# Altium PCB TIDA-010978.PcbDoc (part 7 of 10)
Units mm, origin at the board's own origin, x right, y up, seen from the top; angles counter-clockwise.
Board outline 243.95 x 94.85 mm, 4 copper layers (Top Layer, Mid Layer 1, Mid Layer 2, Bottom Layer), stack 1.623 mm thick; 865 components, 374 nets, 2308 pads, 2132 vias.
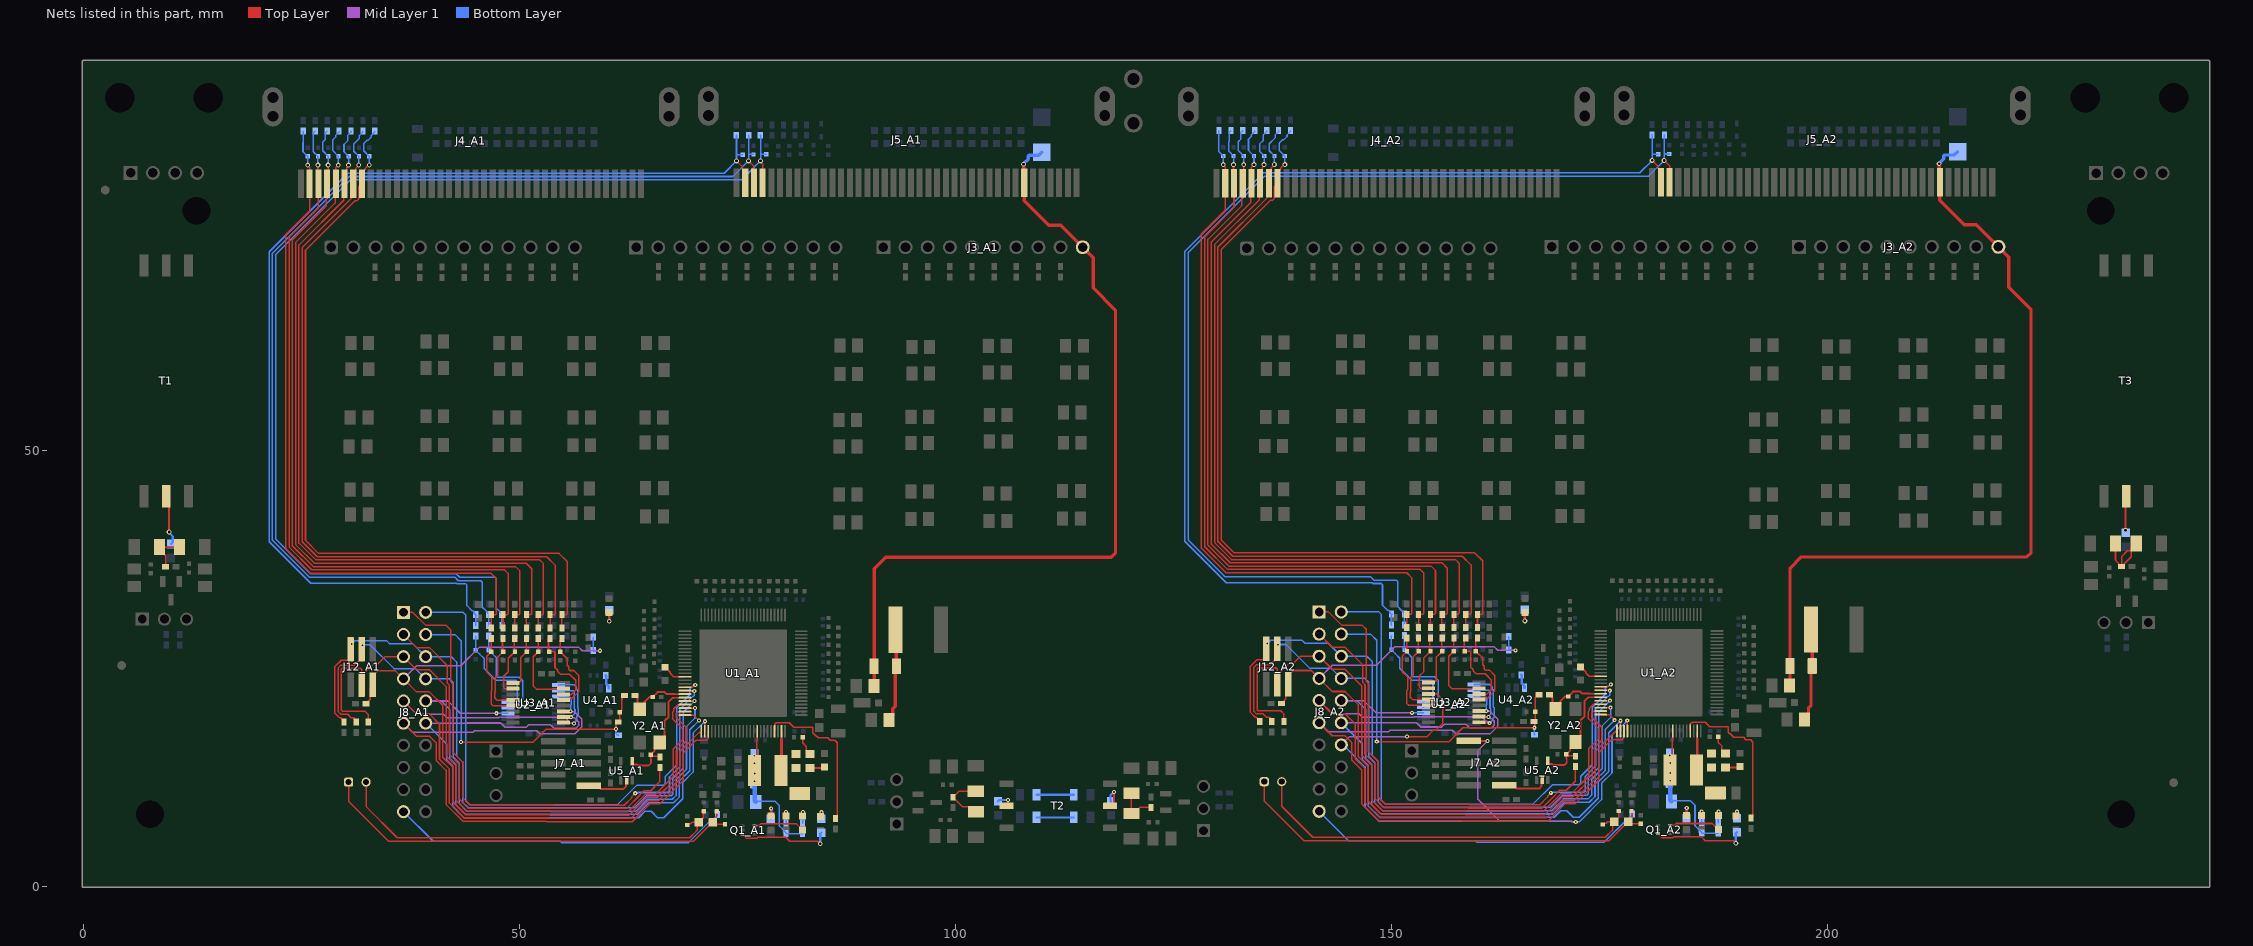
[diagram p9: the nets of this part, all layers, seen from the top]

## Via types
v1: diameter 0.559, hole 0.305, Top Layer to Bottom Layer, tented both sides, 1735 vias
v2: diameter 0.47, hole 0.2, Top Layer to Bottom Layer, tented both sides, 269 vias
v3: diameter 0.5, hole 0.2, Top Layer to Bottom Layer, tented both sides, 128 vias

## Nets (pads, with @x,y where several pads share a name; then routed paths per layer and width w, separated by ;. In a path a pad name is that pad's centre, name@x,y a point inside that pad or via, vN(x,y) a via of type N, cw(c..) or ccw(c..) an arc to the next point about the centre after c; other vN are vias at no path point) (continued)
GPIO8_A2: J7_A2.10 J8_A2.14 U1_A2.79 U3_A2.3 | length 87.7
  Top Layer w0.178: v2(151.794,17.184) 151.839,17.139 154.041,17.139 154.831,17.929 155.107,17.929 155.896,18.718 155.896,21.374 155.182,22.088 154.257,22.088 U3_A2.3@154.243,22.074 ; v2(177.036,19.003) 177.046,18.993 177.046,17.834 U1_A2.79@177.057,17.824
  Top Layer w0.254: J7_A2.10@158.86,16.691 158.867,16.684 160.992,16.684 v2(160.999,16.677)
  Mid Layer 1 w0.178: J8_A2.14@144.243,16.231 145.196,17.184 v2(151.794,17.184) ; v2(160.999,16.677) 159.914,15.592 159.914,9.994 162.459,7.45 170.674,7.45 170.692,7.432 171.096,7.432 v2(171.135,7.394)
  Bottom Layer w0.178: J8_A2.14@144.243,16.231 144.428,16.231 146.963,13.696 146.963,9.073 148.586,7.45 170.674,7.45 170.692,7.432 171.096,7.432 v2(171.135,7.394) ; v2@171.135,7.377 171.19,7.432 171.577,7.432 174.097,9.952 174.097,11.818 175.288,13.009 175.288,17.367 176.305,18.384 176.431,18.384 177.036,18.989 v2(177.036,19.003)
GPIO9_A1: J8_A1.11 U1_A1.78 U2_A1.11 U3_A1.11 | length 77.6
  Top Layer w0.178: J8_A1.11@36.703,18.721 38.204,17.22 39.673,17.22 40.454,16.439 40.454,14.433 41.585,13.302 41.585,11.503 41.585,9.401 43.521,7.466 53.114,7.466 53.156,7.424 62.936,7.424 64.964,9.452 66.097,9.452 68.762,12.117 68.762,15.277 70.244,16.76 71.447,16.76 71.646,16.958 71.646,17.762 U1_A1.78@71.657,17.774 ; U3_A1.11@55.043,20.073 v2(55.846,20.073)
  Mid Layer 1 w0.178: J8_A1.11@36.703,18.721 37.742,17.682 44.668,17.682 44.835,17.848 51.976,17.848 52.347,17.477 56.345,17.477 57.163,18.295 57.163,19.175 56.321,20.017 55.902,20.017 v2(55.846,20.073)
  Bottom Layer w0.178: U2_A1.11@54.473,21.789 54.599,21.663 55.82,21.663 55.924,21.559 55.924,20.841 55.863,20.78 55.863,20.09 v2(55.846,20.073)
GPIO9_A2: J8_A2.11 U1_A2.78 U2_A2.11 U3_A2.11 | length 77.6
  Top Layer w0.178: J8_A2.11@141.703,18.771 143.204,17.27 144.673,17.27 145.454,16.489 145.454,14.483 146.585,13.352 146.585,11.553 146.585,9.451 148.521,7.516 158.114,7.516 158.156,7.474 167.936,7.474 169.964,9.502 171.097,9.502 173.762,12.167 173.762,15.327 175.244,16.81 176.447,16.81 176.646,17.008 176.646,17.812 U1_A2.78@176.657,17.824 ; U3_A2.11@160.043,20.124 160.046,20.121 160.861,20.121 v2(160.863,20.118)
  Mid Layer 1 w0.178: J8_A2.11@141.703,18.771 142.742,17.732 149.668,17.732 149.835,17.898 156.976,17.898 157.347,17.527 161.345,17.527 162.163,18.345 162.163,19.225 161.325,20.063 160.919,20.063 v2(160.863,20.118)
  Bottom Layer w0.178: U2_A2.11@159.473,21.839 159.599,21.713 160.82,21.713 160.924,21.609 160.924,20.891 160.863,20.83 v2(160.863,20.118)
GPIO10_A1: J8_A1.12 U1_A1.77 U2_A1.10 U3_A1.10 | length 76
  Top Layer w0.178: U3_A1.10@55.043,19.424 55.052,19.414 55.897,19.414 v2(55.906,19.405) ; U1_A1.77@71.257,17.774 71.264,17.78 71.264,18.931 v2(71.271,18.938)
  Mid Layer 1 w0.178: J8_A1.12@39.243,18.721 43.957,18.721 43.971,18.735 47.85,18.735 48.359,18.226 50.752,18.226 51.05,18.525 53.574,18.525 53.955,18.144 56.478,18.144 56.785,18.451 56.785,18.885 56.321,19.35 55.962,19.35 v2(55.906,19.405)
  Bottom Layer w0.178: J8_A1.12@39.243,18.721 41.65,16.314 41.65,14.494 42.341,13.802 42.341,9.18 43.65,7.871 63.669,7.871 64.411,8.613 65.108,8.613 65.842,7.878 66.539,7.878 68.719,10.058 68.719,11.924 69.911,13.116 69.911,17.578 v2(71.271,18.938) ; U2_A1.10@54.473,22.439 54.483,22.449 56.197,22.449 56.302,22.345 56.302,20.357 56.37,20.29 56.37,19.856 55.919,19.405 v2(55.906,19.405)
GPIO10_A2: J8_A2.12 U1_A2.77 U2_A2.10 U3_A2.10 | length 75.9
  Top Layer w0.178: U3_A2.10@160.043,19.474 160.062,19.455 161.103,19.455 v2(161.122,19.436) ; U1_A2.77@176.257,17.824 176.264,17.83 176.264,18.981 v2(176.271,18.988)
  Mid Layer 1 w0.178: J8_A2.12@144.243,18.771 148.957,18.771 148.971,18.785 152.85,18.785 153.359,18.276 155.752,18.276 156.05,18.575 158.574,18.575 158.955,18.194 161.478,18.194 161.785,18.501 161.785,18.935 161.478,19.242 161.395,19.242 161.201,19.436 v2(161.122,19.436)
  Bottom Layer w0.178: J8_A2.12@144.243,18.771 146.65,16.364 146.65,14.544 147.341,13.852 147.341,9.23 148.65,7.921 168.669,7.921 169.411,8.663 170.108,8.663 170.842,7.928 171.539,7.928 173.719,10.108 173.719,11.974 174.911,13.166 174.911,17.628 v2(176.271,18.988) ; U2_A2.10@159.473,22.489 159.483,22.499 161.197,22.499 161.302,22.395 161.302,20.421 161.387,20.335 161.387,19.78 161.122,19.515 v2(161.122,19.436)
GPIO11_A1: J8_A1.9 U1_A1.76 U2_A1.9 U3_A1.9 | length 79
  Top Layer w0.178: J8_A1.9@36.703,21.261 38.204,19.76 39.673,19.76 40.832,18.601 40.832,14.59 41.963,13.458 41.963,11.659 41.963,9.558 43.677,7.844 53.271,7.844 53.312,7.802 62.78,7.802 64.815,9.837 65.948,9.837 68.384,12.274 68.384,15.434 70.594,17.644 70.846,17.644 70.857,17.655 U1_A1.76@70.857,17.774 ; U3_A1.9@55.043,18.774 55.096,18.721 56.208,18.721 v2(56.261,18.668)
  Mid Layer 1 w0.178: J8_A1.9@36.703,21.261 38.204,19.76 41.268,19.76 41.703,19.326 47.565,19.326 47.648,19.409 55.162,19.409 55.847,18.724 56.205,18.724 v2(56.261,18.668)
  Bottom Layer w0.178: U2_A1.9@54.473,23.089 54.483,23.099 56.252,23.099 56.529,22.822 56.529,22.652 56.679,22.502 56.679,20.514 56.747,20.446 56.747,19.699 56.569,19.52 56.569,19.054 56.261,18.747 v2(56.261,18.668)
GPIO11_A2: J8_A2.9 U1_A2.76 U2_A2.9 U3_A2.9 | length 79
  Top Layer w0.178: J8_A2.9@141.703,21.311 143.204,19.81 144.673,19.81 145.832,18.651 145.832,14.64 146.963,13.508 146.963,11.709 146.963,9.608 148.677,7.894 158.271,7.894 158.312,7.852 167.78,7.852 169.815,9.887 170.948,9.887 173.384,12.324 173.384,15.484 175.595,17.694 175.846,17.694 175.857,17.705 U1_A2.76@175.857,17.824 ; U3_A2.9@160.043,18.824 160.096,18.771 161.208,18.771 v2(161.261,18.718)
  Mid Layer 1 w0.178: J8_A2.9@141.703,21.311 143.204,19.81 146.268,19.81 146.703,19.376 152.565,19.376 152.648,19.459 160.359,19.459 160.905,18.912 160.988,18.912 161.182,18.718 v2(161.261,18.718)
  Bottom Layer w0.178: U2_A2.9@159.473,23.139 159.483,23.149 161.252,23.149 161.529,22.872 161.529,22.702 161.679,22.552 161.679,20.577 161.765,20.492 161.765,19.396 161.607,19.239 161.607,19.081 161.261,18.735 v2(161.261,18.718)
GPIO12_A1: J8_A1.10 U1_A1.75 U2_A1.3 | length 62.9
  Top Layer w0.178: U1_A1.75@68.982,19.649 69.972,19.649 70.596,19.024 v2(70.596,19.013)
  Mid Layer 1 w0.178: J8_A1.10@39.243,21.261 41.8,21.261 43.211,19.849 v2(47.348,19.849)
  Bottom Layer w0.178: J8_A1.10@39.243,21.261 41.024,21.261 42.028,20.257 42.028,14.65 42.719,13.959 42.719,12.542 42.719,10.939 42.719,9.336 43.806,8.249 45.409,8.249 47.012,8.249 63.513,8.249 64.871,9.607 67.691,9.607 68.341,10.258 68.341,12.081 69.533,13.272 69.533,17.967 70.579,19.013 v2(70.596,19.013) ; v2(47.348,19.849) 47.353,19.844 48.668,19.844 U2_A1.3@48.673,19.839
GPIO12_A2: J8_A2.10 U1_A2.75 U2_A2.3 | length 62.9
  Top Layer w0.178: U1_A2.75@173.982,19.699 174.972,19.699 175.596,19.074 v2(175.596,19.063)
  Mid Layer 1 w0.178: J8_A2.10@144.243,21.311 146.8,21.311 148.211,19.899 v2(152.348,19.899)
  Bottom Layer w0.178: J8_A2.10@144.243,21.311 146.024,21.311 147.028,20.307 147.028,14.7 147.719,14.009 147.719,12.592 147.719,10.989 147.719,9.386 148.806,8.299 150.409,8.299 152.012,8.299 168.513,8.299 169.871,9.657 172.691,9.657 173.341,10.308 173.341,12.131 174.533,13.322 174.533,18.017 175.579,19.063 v2(175.596,19.063) ; v2(152.348,19.899) 152.353,19.894 153.668,19.894 U2_A2.3@153.673,19.889
GPIO13_A1: C94_A1.1 J8_A1.7 J12_A1.2 R196_A1.1 R236_A1.2 U1_A1.74 | length 89
  Top Layer w0.178: R236_A1.2@32.386,20.93 32.481,21.026 32.481,21.044 32.902,21.464 32.902,22.857 33.248,23.204 33.248,24.229 33.726,24.707 35.797,24.707 J8_A1.7@36.703,23.801 38.204,22.3 39.673,22.3 41.21,20.763 41.21,14.819 42.341,13.688 42.341,11.816 42.341,9.714 43.834,8.221 53.427,8.221 53.469,8.18 62.592,8.18 64.627,10.215 65.791,10.215 68.007,12.43 68.007,15.59 69.115,16.699 69.115,18.209 67.968,19.356 67.968,19.839 68.167,20.037 68.971,20.037 U1_A1.74@68.982,20.049
  Mid Layer 1 w0.178: J8_A1.7@36.703,23.801 38.204,25.302 43.278,25.302 45.42,27.444 56.762,27.444 57.188,27.018 v2(59.232,27.018)
  Bottom Layer w0.178: R196_A1.1@58.452,28.584 58.452,27.065 C94_A1.1@58.455,27.061 58.498,27.018 v2(59.232,27.018)
GPIO13_A2: C94_A2.1 J8_A2.7 J12_A2.2 R196_A2.1 R236_A2.2 U1_A2.74 | length 89
  Top Layer w0.178: R236_A2.2@137.386,20.98 137.481,21.076 137.481,21.094 137.902,21.514 137.902,22.907 138.248,23.254 138.248,24.279 138.726,24.757 140.797,24.757 J8_A2.7@141.703,23.851 143.204,22.35 144.673,22.35 146.21,20.813 146.21,14.869 147.341,13.738 147.341,11.866 147.341,9.764 148.834,8.271 158.427,8.271 158.469,8.23 167.592,8.23 169.627,10.265 170.791,10.265 173.007,12.48 173.007,15.64 174.115,16.749 174.115,18.259 172.968,19.406 172.968,19.889 173.167,20.087 173.971,20.087 U1_A2.74@173.982,20.099
  Mid Layer 1 w0.178: J8_A2.7@141.703,23.851 143.204,25.352 148.278,25.352 150.42,27.494 161.762,27.494 162.188,27.068 v2(164.232,27.068)
  Bottom Layer w0.178: R196_A2.1@163.452,28.634 163.452,27.115 C94_A2.1@163.455,27.111 163.498,27.068 v2(164.232,27.068)
GPIO14_A1: J8_A1.8 J12_A1.3 R235_A1.1 U1_A1.73 | length 76.8
  Top Layer w0.178: R235_A1.1@31.283,18.864 31.072,19.075 31.072,19.35 30.68,19.35 30.302,19.728 29.53,19.728 29.205,20.053 29.205,25.047 29.53,25.372 31.102,25.372 31.901,26.171 J12_A1.3@31.901,27.196 31.999,27.294 v2(31.999,27.665) ; U1_A1.73@68.982,20.449 v2(70.131,20.449)
  Bottom Layer w0.178: v2(31.999,27.665) 32.022,27.687 32.9,27.687 35.605,24.982 38.061,24.982 J8_A1.8@39.243,23.801 41.963,23.801 42.405,23.358 42.405,14.806 43.096,14.115 43.096,12.699 43.096,11.096 43.096,9.493 43.963,8.627 45.566,8.627 47.168,8.627 63.356,8.627 64.714,9.985 67.534,9.985 67.964,10.414 67.964,12.237 69.155,13.429 69.155,18.33 70.131,19.306 v2(70.131,20.449)
GPIO14_A2: J8_A2.8 J12_A2.3 R235_A2.1 U1_A2.73 | length 76.8
  Top Layer w0.178: R235_A2.1@136.283,18.914 136.072,19.125 136.072,19.4 135.68,19.4 135.302,19.778 134.53,19.778 134.205,20.103 134.205,25.097 134.53,25.422 136.102,25.422 136.901,26.221 J12_A2.3@136.901,27.246 136.999,27.344 v2(136.999,27.715) ; U1_A2.73@173.982,20.499 v2(175.131,20.499)
  Bottom Layer w0.178: v2(136.999,27.715) 137.022,27.737 137.9,27.737 140.605,25.032 143.061,25.032 J8_A2.8@144.243,23.851 146.963,23.851 147.405,23.408 147.405,14.856 148.096,14.165 148.096,12.749 148.096,11.146 148.096,9.543 148.963,8.677 150.566,8.677 152.168,8.677 168.356,8.677 169.714,10.035 172.534,10.035 172.964,10.464 172.964,12.287 174.155,13.479 174.155,18.38 175.131,19.356 v2(175.131,20.499)
GPIO15_A1: J8_A1.5 J12_A1.4 R234_A1.1 U1_A1.72 | length 75.9
  Top Layer w0.178: J12_A1.4@31.901,23.126 J12_A1.4@31.901,24.151 ; R234_A1.1@32.668,18.864 32.668,19.706 32.296,20.078 30.487,20.078 30.459,20.106 29.687,20.106 29.583,20.21 29.583,24.89 29.687,24.994 31.796,24.994 31.901,24.89 J12_A1.4@31.901,24.151 ; U1_A1.72@68.982,20.849 68.971,20.837 68.167,20.837 67.7,20.371 67.7,20.105 67.59,19.995 67.59,19.199 68.737,18.052 68.737,16.855 67.629,15.747 67.629,12.587 65.635,10.593 64.452,10.593 64.18,10.321 64.18,10.302 62.435,8.558 53.625,8.558 53.584,8.599 43.99,8.599 42.719,9.871 42.719,13.844 41.588,14.975 41.588,22.925 39.673,24.84 38.204,24.84 J8_A1.5@36.703,26.341 34.571,26.341 33.742,25.512 33.262,25.512 J12_A1.4@31.901,24.151
GPIO15_A2: J8_A2.5 J12_A2.4 R234_A2.1 U1_A2.72 | length 75.9
  Top Layer w0.178: J12_A2.4@136.901,23.176 J12_A2.4@136.901,24.201 ; R234_A2.1@137.668,18.914 137.668,19.756 137.296,20.128 135.487,20.128 135.459,20.156 134.687,20.156 134.583,20.26 134.583,24.94 134.687,25.044 136.796,25.044 136.901,24.94 J12_A2.4@136.901,24.201 ; U1_A2.72@173.982,20.899 173.971,20.887 173.167,20.887 172.7,20.421 172.7,20.155 172.59,20.045 172.59,19.249 173.737,18.102 173.737,16.905 172.629,15.797 172.629,12.637 170.635,10.643 169.452,10.643 169.18,10.371 169.18,10.352 167.435,8.608 158.625,8.608 158.584,8.649 148.99,8.649 147.719,9.921 147.719,13.894 146.588,15.025 146.588,22.975 144.673,24.89 143.204,24.89 J8_A2.5@141.703,26.391 139.571,26.391 138.742,25.562 138.262,25.562 J12_A2.4@136.901,24.201
GPIO16_A1: J8_A1.6 J12_A1.5 R233_A1.1 U1_A1.71 | length 78.6
  Top Layer w0.178: R233_A1.1@29.883,18.864 29.883,18.964 29.496,19.35 29.374,19.35 28.827,19.897 28.827,25.203 29.566,25.942 30.349,25.942 30.631,26.223 J12_A1.5@30.631,27.196 J12_A1.5@30.631,28.221 ; J8_A1.6@39.127,26.341 J8_A1.6@39.243,26.341 ; U1_A1.71@68.982,21.249 v2(70.069,21.249)
  Bottom Layer w0.178: v2(30.763,27.796) 31.156,28.188 34.747,28.188 35.093,27.842 37.742,27.842 J8_A1.6@39.243,26.341 42.173,26.341 42.783,25.731 42.783,14.963 43.474,14.272 43.474,9.649 44.119,9.004 63.2,9.004 64.581,10.386 67.401,10.386 67.586,10.571 67.586,12.394 68.777,13.585 68.777,19.957 v2(70.069,21.249)
GPIO16_A2: J8_A2.6 J12_A2.5 R233_A2.1 U1_A2.71 | length 78.6
  Top Layer w0.178: R233_A2.1@134.883,18.914 134.883,19.014 134.496,19.4 134.374,19.4 133.827,19.947 133.827,25.253 134.566,25.992 135.349,25.992 135.631,26.273 J12_A2.5@135.631,27.246 J12_A2.5@135.631,28.271 ; J8_A2.6@144.127,26.391 J8_A2.6@144.243,26.391 ; U1_A2.71@173.982,21.299 v2(175.069,21.299)
  Bottom Layer w0.178: v2(135.763,27.846) 136.156,28.238 139.747,28.238 140.093,27.892 142.742,27.892 J8_A2.6@144.243,26.391 147.173,26.391 147.783,25.781 147.783,15.013 148.474,14.322 148.474,9.699 149.119,9.054 168.2,9.054 169.581,10.436 172.401,10.436 172.586,10.621 172.586,12.444 173.777,13.635 173.777,20.007 v2(175.069,21.299)
GPIO17_A1: J8_A1.3 R71_A1.2 | length 48.7
  Top Layer w0.178: J8_A1.3@36.703,28.881 38.204,27.38 39.673,27.38 41.722,25.331 41.722,23.326 41.965,23.082 41.965,15.132 43.096,14.001 43.096,12.164 43.096,10.027 44.147,8.977 53.74,8.977 53.782,8.935 62.279,8.935 63.802,10.459 63.802,10.477 64.296,10.971 65.05,10.971 66.073,11.994 66.073,13.593 R71_A1.2@66.111,13.631
GPIO17_A2: J8_A2.3 R71_A2.2 | length 48.8
  Top Layer w0.178: J8_A2.3@141.703,28.931 143.204,27.43 144.673,27.43 146.722,25.381 146.722,23.376 146.965,23.132 146.965,15.182 148.096,14.051 148.096,12.214 148.096,10.077 149.147,9.027 158.74,9.027 158.782,8.985 167.279,8.985 168.802,10.509 168.802,10.527 169.296,11.021 170.05,11.021 171.073,12.044 171.073,13.69 R71_A2.2@171.104,13.721
GPIO17_OSC_A1: C124_A1.1 R71_A1.1 U1_A1.70 U5_A1.4 Y2_A1.1 | length 13.8
  Top Layer w0.178: C124_A1.1@65.047,15.088 65.208,14.927 65.488,14.927 65.506,14.91 65.983,14.91 66.032,14.91 R71_A1.1@66.111,14.831 ; 67.591,21.618 67.617,21.644 68.965,21.644 U1_A1.70@68.971,21.637
  Top Layer w0.203: U5_A1.4@62.937,14.357 62.937,14.082 63.035,13.984 63.43,13.984 63.555,13.859 64.82,13.859 65.09,14.128 65.09,14.573 65.047,14.615 C124_A1.1@65.047,15.088 65.496,15.537 65.496,15.915 Y2_A1.1@66.094,16.513
  Top Layer w0.229: Y2_A1.1@66.094,16.513 66.66,17.079 66.66,18.999 66.86,19.199 66.896,19.199 67.114,19.417 67.114,21.159 67.574,21.618 67.591,21.618
GPIO17_OSC_A2: C124_A2.1 R71_A2.1 U1_A2.70 U5_A2.4 Y2_A2.1 | length 13.8
  Top Layer w0.178: C124_A2.1@170.047,15.138 170.208,14.977 170.488,14.977 170.506,14.96 171.066,14.96 R71_A2.1@171.104,14.921 ; 172.591,21.668 172.617,21.694 173.965,21.694 U1_A2.70@173.971,21.687
  Top Layer w0.203: U5_A2.4@167.937,14.407 167.937,14.132 168.035,14.034 168.43,14.034 168.555,13.909 169.82,13.909 170.09,14.178 170.09,14.623 170.047,14.665 C124_A2.1@170.047,15.138 170.496,15.587 170.496,15.965 Y2_A2.1@171.094,16.563
  Top Layer w0.229: Y2_A2.1@171.094,16.563 171.66,17.129 171.66,19.049 171.86,19.249 171.896,19.249 172.114,19.467 172.114,21.209 172.574,21.668 172.591,21.668
GPIO18_A1: C155_A1.2 J8_A1.4 R56_A1.1 R76_A1.2 R77_A1.2 | length 39.8
  Top Layer w0.178: v2(43.307,16.545) 51.59,16.545 53.084,18.038 v2(61.074,18.038) 61.074,18.633 61.392,18.951 61.446,18.951 61.494,19 61.483,19.011 C155_A1.2@61.483,19.948 ; C155_A1.2@61.483,19.959 61.722,20.197 61.722,21.376 61.761,21.415 61.761,21.671 61.972,21.882 R77_A1.2@62.067,21.882 ; R77_A1.2@61.856,22.051 R77_A1.2@62.028,21.88
  Bottom Layer w0.178: J8_A1.4@39.243,28.881 42.594,28.881 43.307,28.168 v2(43.307,16.545) ; v2(61.074,18.038) 61.074,17.552 61.285,17.341 R56_A1.1@61.367,17.341
GPIO18_A2: C155_A2.2 J8_A2.4 R56_A2.1 R76_A2.2 R77_A2.2 | length 39.9
  Top Layer w0.178: v2(148.307,16.595) 156.59,16.595 158.181,18.185 v2(166.384,18.185) 166.446,18.185 166.446,19.001 166.494,19.05 166.483,19.061 C155_A2.2@166.483,19.998 ; C155_A2.2@166.483,20.009 166.494,20.02 166.494,20.777 166.502,20.784 166.502,21.651 166.81,21.959 R77_A2.2@166.81,21.964 ; R77_A2.2@166.604,22.175 166.815,21.964 R77_A2.2@166.915,21.964
  Bottom Layer w0.178: J8_A2.4@144.243,28.931 147.594,28.931 148.307,28.218 v2(148.307,16.595) ; v2(166.384,18.185) 166.384,17.424 R56_A2.1@166.417,17.391
GPIO18_OSC_A1: C128_A1.1 R77_A1.1 U1_A1.69 Y2_A1.3 | length 8.2
  Top Layer w0.178: 67.795,22.047 U1_A1.69@68.98,22.047
  Top Layer w0.229: R77_A1.1@63.267,21.882 63.367,21.882 63.552,21.696 63.552,20.762 63.557,20.757 63.454,20.654 Y2_A1.3@63.794,20.313 64.367,20.886 64.367,21.189 64.921,21.742 65.251,21.742 C128_A1.1@65.272,21.722 65.836,22.286 66.652,22.286 66.891,22.047 67.795,22.047
GPIO18_OSC_A2: C128_A2.1 R77_A2.1 U1_A2.69 Y2_A2.3 | length 8.2
  Top Layer w0.178: 172.795,22.097 U1_A2.69@173.98,22.097
  Top Layer w0.229: R77_A2.1@168.115,21.964 168.215,21.964 168.401,21.779 168.401,21.688 168.454,21.635 168.454,20.704 Y2_A2.3@168.794,20.363 169.367,20.936 169.367,21.239 169.921,21.792 170.251,21.792 C128_A2.1@170.272,21.772 170.836,22.336 171.652,22.336 171.891,22.097 172.795,22.097
GPIO19_A1: J8_A1.1 U1_A1.68 | length 65.3
  Top Layer w0.178: J8_A1.1@36.703,31.421 37.774,31.421 39.275,29.92 41.614,29.92 42.099,29.434 42.099,23.482 42.343,23.238 42.343,15.403 43.474,14.272 43.474,10.184 44.303,9.355 53.897,9.355 53.938,9.313 62.026,9.313 62.9,10.187 62.9,10.298 v2(63.278,10.676) ; U1_A1.68@68.35,22.437 68.361,22.449 U1_A1.68@68.982,22.449 68.993,22.437 69.999,22.437 v2(70.04,22.396)
  Bottom Layer w0.178: v2(63.278,10.676) 63.334,10.731 63.539,10.731 63.571,10.764 67.104,10.764 67.208,10.868 67.208,12.55 68.399,13.742 68.399,20.32 69.852,21.772 69.936,21.772 70.04,21.877 v2(70.04,22.396)
GPIO19_A2: J8_A2.1 U1_A2.68 | length 65.3
  Top Layer w0.178: J8_A2.1@141.703,31.471 142.774,31.471 144.275,29.97 146.614,29.97 147.099,29.484 147.099,23.532 147.343,23.288 147.343,15.453 148.474,14.322 148.474,10.234 149.303,9.405 158.897,9.405 158.938,9.363 167.026,9.363 167.9,10.237 167.9,10.348 v2(168.278,10.726) ; U1_A2.68@173.35,22.487 173.361,22.499 U1_A2.68@173.982,22.499 173.993,22.487 174.999,22.487 v2(175.04,22.446)
  Bottom Layer w0.178: v2(168.278,10.726) 168.334,10.781 168.539,10.781 168.571,10.814 172.104,10.814 172.208,10.918 172.208,12.6 173.399,13.792 173.399,20.37 174.852,21.822 174.936,21.822 175.04,21.927 v2(175.04,22.446)
GPIO20_A1: J8_A1.2 U1_A1.67 | length 64.2
  Top Layer w0.178: U1_A1.67@68.982,22.849 68.993,22.86 69.797,22.86 69.969,23.031 70.1,23.031 v2(70.156,23.087)
  Bottom Layer w0.178: J8_A1.2@39.243,31.421 43.566,31.421 43.852,31.134 43.852,9.806 44.276,9.382 61.244,9.382 63.478,11.616 66.523,11.616 66.697,11.791 66.697,12.574 68.022,13.898 68.022,20.476 69.517,21.971 69.517,22.633 69.803,22.919 69.91,22.919 70.077,23.087 v2(70.156,23.087)
GPIO20_A2: J8_A2.2 U1_A2.67 | length 64.2
  Top Layer w0.178: U1_A2.67@173.982,22.899 173.993,22.91 174.797,22.91 174.969,23.081 175.1,23.081 v2(175.156,23.137)
  Bottom Layer w0.178: J8_A2.2@144.243,31.471 148.566,31.471 148.852,31.184 148.852,9.856 149.276,9.432 166.244,9.432 168.478,11.666 171.523,11.666 171.697,11.841 171.697,12.624 173.022,13.948 173.022,20.526 174.517,22.021 174.517,22.683 174.803,22.969 174.91,22.969 175.077,23.137 v2(175.156,23.137)
GPIO_R_A1: J8_A1.19 R105_A1.1 | length 38.8
  Bottom Layer w0.178: J8_A1.19@36.703,8.561 40.102,5.162 54.672,5.162 54.816,5.017 69.386,5.017 72.086,7.718 72.247,7.718 72.697,8.168 R105_A1.1@72.697,8.226
GPIO_R_A2: J8_A2.19 R105_A2.1 | length 38.8
  Bottom Layer w0.178: J8_A2.19@141.703,8.611 145.102,5.212 159.672,5.212 159.816,5.067 174.386,5.067 177.085,7.766 177.201,7.766 177.609,8.174 R105_A2.1@177.609,8.274
LDOIN_A1: C11_A1.2 C16_A1.2 C17_A1.2 C18_A1.1 L2_A1.2 R126_A1.2 R129_A1.2 U1_A1.92 | length 15.5
  Top Layer w0.178: L2_A1.2@76.943,13.29 77.202,13.549 77.202,16.769 77.257,16.824 U1_A1.92@77.257,17.774
  Bottom Layer w0.178: C18_A1.1@77.096,9.691 77.179,9.774 79.29,9.774 79.81,9.255 79.81,6.914 80.153,6.571 80.161,6.571 80.572,6.16 R129_A1.2@80.572,6.06 R126_A1.2@82.468,6.06
  Bottom Layer w0.254: C11_A1.2@76.839,11.652 76.915,11.729 76.915,12.022 v2(76.956,12.063)
  Bottom Layer w0.508: C11_A1.2@76.839,11.652 76.967,11.523 76.967,9.82 C18_A1.1@77.096,9.691
  other v2: 76.978,12.955 76.956,14.108 76.925,14.969
LDOIN_A2: C11_A2.2 C16_A2.2 C17_A2.2 C18_A2.1 L2_A2.2 R126_A2.2 R129_A2.2 U1_A2.92 | length 15.5
  Top Layer w0.178: L2_A2.2@181.943,13.34 182.202,13.599 182.202,16.819 182.257,16.874 U1_A2.92@182.257,17.824
  Bottom Layer w0.178: C18_A2.1@182.096,9.741 182.179,9.824 184.29,9.824 184.81,9.305 184.81,6.964 185.153,6.621 185.161,6.621 185.572,6.21 R129_A2.2@185.572,6.11 R126_A2.2@187.468,6.11
  Bottom Layer w0.254: C11_A2.2@181.839,11.702 181.915,11.779 181.915,12.072 v2(181.956,12.113)
  Bottom Layer w0.508: C11_A2.2@181.839,11.702 181.967,11.573 181.967,9.87 C18_A2.1@182.096,9.741
  other v2: 181.978,13.005 181.956,14.158 181.925,15.019
MCU_PWM_A1: J7_A1.1 U5_A1.2 | length 5.3
  Top Layer w0.229: J7_A1.1@57.93,11.561 58.955,11.561 59.211,11.305 59.211,11.297 59.345,11.163 61.925,11.163 62.201,11.439 62.201,12.071 U5_A1.2@62.287,12.157
MCU_PWM_A2: J7_A2.1 U5_A2.2 | length 5.3
  Top Layer w0.229: J7_A2.1@162.93,11.611 163.955,11.611 164.211,11.355 164.211,11.347 164.345,11.213 166.925,11.213 167.201,11.489 167.201,12.121 U5_A2.2@167.287,12.207
MODE_A1: R79_A1.2 U1_A1.97 | length 18.2
  Top Layer w0.152: U1_A1.97@79.257,17.774 79.281,17.797 79.281,18.584 79.472,18.775 80.964,18.775 81.479,18.259 83.553,18.259 83.642,18.17 83.642,17.599 83.804,17.437 83.827,17.437 84.238,17.026 85.371,17.026 85.648,16.749 86.18,16.749 86.457,16.473 86.457,7.991 R79_A1.2@86.233,7.767
MODE_A2: R79_A2.2 U1_A2.97 | length 18.2
  Top Layer w0.152: U1_A2.97@184.257,17.824 184.281,17.847 184.281,18.634 184.472,18.825 185.964,18.825 186.479,18.309 188.553,18.309 188.642,18.22 188.642,17.649 188.804,17.487 188.827,17.487 189.238,17.076 190.371,17.076 190.648,16.799 191.18,16.799 191.457,16.523 191.457,8.041 R79_A2.2@191.233,7.817
NetAVDD_LED1_A1_2: AVDD_LED1_A1.2 R128_A1.2 | length 2.1
  Top Layer w0.254: AVDD_LED1_A1.2@78.832,8.062 78.865,8.095 v2(78.865,8.934)
  Bottom Layer w0.254: R128_A1.2@78.833,7.764 78.865,7.796 v2(78.865,8.934)
NetAVDD_LED1_A2_2: AVDD_LED1_A2.2 R128_A2.2 | length 2.1
  Top Layer w0.254: AVDD_LED1_A2.2@183.832,8.113 183.865,8.145 v2(183.865,8.984)
  Bottom Layer w0.254: R128_A2.2@183.833,7.814 183.865,7.846 v2(183.865,8.984)
NetC1_2: C1.2 C2.1 | length 4.3
  Bottom Layer w0.254: C1.2@109.291,10.497 C2.1@113.566,10.497
NetC3_2: C3.2 T1.5 | length 5.9
  Top Layer w0.254: T1.5@9.5,44.75 9.82,44.43 v1(9.82,40.643)
  Bottom Layer w0.254: v1(9.82,40.643) 9.82,40.565 10.248,40.137 10.248,39.479 C3.2@10.033,39.263
NetC4_2: C4.2 T2.2 | length 1.9
  Top Layer w0.254: T2.2@105.863,9.242 106.012,9.392 v2(106.012,9.914)
  Bottom Layer w0.254: C4.2@104.875,9.746 105.042,9.914 v2(106.012,9.914)
NetC5_2: C5.2 T2.5 | length 3.2
  Top Layer w0.254: T2.5@117.737,9.242 117.936,9.242 118.189,9.495 v2(118.189,10.834)
  Bottom Layer w0.254: C5.2@117.849,9.746 117.764,9.831 117.764,10.41 v2(118.189,10.834)
NetC6_2: C6.2 C7.1 | length 4.3
  Bottom Layer w0.254: C6.2@109.291,7.915 C7.1@113.566,7.915
NetC8_2: C8.2 T3.5 | length 3.9
  Top Layer w0.254: v1(234.174,40.834) 234.174,44.668 T3.5@234.256,44.75
NetC10_A1_1: C10_A1.1 R6_A1.2 R7_A1.1 | length 10.8
  Top Layer w0.381: R7_A1.1@92.374,19.092 92.819,19.536 92.819,20.369 93.104,20.654 93.104,25.121 R6_A1.2@93.227,25.245 93.227,29.058 93.077,29.209 93.077,29.375 C10_A1.1@93.119,29.417
NetC10_A2_1: C10_A2.1 R6_A2.2 R7_A2.1 | length 10.7
  Top Layer w0.381: R7_A2.1@197.374,19.142 197.819,19.586 197.819,20.419 198.104,20.704 198.104,25.127 R6_A2.2@198.254,25.277 198.254,28.917 198.104,29.068 C10_A2.1@198.104,29.452
NetC20_A1_2: C20_A1.2 R20_A1.1 | length 1.7
  Top Layer w0.254: R20_A1.1@83.307,13.585 84.828,13.585 C20_A1.2@84.958,13.715
NetC20_A2_2: C20_A2.2 R20_A2.1 | length 1.7
  Top Layer w0.254: R20_A2.1@188.307,13.635 189.828,13.635 C20_A2.2@189.958,13.765
NetC31_A1_1: C31_A1.1 R50_A1.2 | length 2.3
  Top Layer w0.178: C31_A1.1@82.484,17.092 82.484,16.46 82.896,16.048 82.896,15.576 83.282,15.19 R50_A1.2@83.307,15.19
NetC31_A2_1: C31_A2.1 R50_A2.2 | length 2.3
  Top Layer w0.178: C31_A2.1@187.484,17.142 187.484,16.51 187.896,16.098 187.896,15.626 188.282,15.24 R50_A2.2@188.307,15.24
NetC142_A1_1: C142_A1.1 R215_A1.1 R221_A1.2 | length 4.8
  Top Layer w0.178: C142_A1.1@9.433,36.666 9.444,36.666 9.444,37.916 8.728,38.632 R221_A1.2@8.728,38.907 R215_A1.1@11.023,38.907
NetC142_A2_1: C142_A2.1 R215_A2.1 R221_A2.2 | length 4.9
  Top Layer w0.178: R215_A2.1@120.177,10.662 R221_A2.2@120.177,8.366 120.452,8.366 121.169,9.082 C142_A2.1@122.523,9.082
NetC143_A1_2: C143_A1.2 R218_A1.1 R222_A1.2 | length 6.3
  Top Layer w0.178: R218_A1.1@102.319,10.921 100.408,10.921 100.019,10.533 99.919,10.533 99.708,10.321 C143_A1.2@99.708,10.221 99.708,10.121 99.919,9.91 100.019,9.91 100.823,9.107 101.774,9.107 R222_A1.2@102.335,8.546
NetC143_A2_2: C143_A2.2 R218_A2.1 R222_A2.2 | length 12.9
  Top Layer w0.178: 233.031,37.392 R218_A2.1@233.031,39.303 233.031,37.392 ; 233.031,37.392 233.42,37.003 ; 233.031,37.392 233.42,37.003 ; C143_A2.2@233.42,36.903 C143_A2.2@233.631,36.692 ; C143_A2.2@233.42,36.903 233.42,37.003 ; C143_A2.2@233.42,36.903 C143_A2.2@233.631,36.692 ; C143_A2.2@233.42,36.903 233.42,37.003 ; C143_A2.2@233.631,36.692 C143_A2.2@233.731,36.692 ; C143_A2.2@233.631,36.692 C143_A2.2@233.731,36.692 ; C143_A2.2@233.731,36.692 233.831,36.692 234.042,36.903 234.042,37.003 234.845,37.807 234.845,38.758 R222_A2.2@235.407,39.319 235.407,39.044 234.845,38.483 234.379,38.483 233.763,37.866 233.763,36.724 C143_A2.2@233.731,36.692
NetDVDD_LED1_A1_1: DVDD_LED1_A1.1 Q1_A1.6 | length 5.9
  Top Layer w0.178: Q1_A1.6@76.937,6.965 77.452,6.965 77.65,7.163 81.778,7.163 DVDD_LED1_A1.1@82.479,6.462
NetDVDD_LED1_A1_2: DVDD_LED1_A1.2 R126_A1.1 | length 1.8
  Top Layer w0.178: DVDD_LED1_A1.2@82.479,8.062 82.519,8.102 v2(82.519,8.524)
  Bottom Layer w0.178: R126_A1.1@82.468,7.26 82.468,8.474 v2(82.519,8.524)
NetDVDD_LED1_A2_1: DVDD_LED1_A2.1 Q1_A2.6 | length 5.9
  Top Layer w0.178: Q1_A2.6@181.937,7.015 182.452,7.015 182.65,7.213 186.778,7.213 DVDD_LED1_A2.1@187.479,6.513
NetDVDD_LED1_A2_2: DVDD_LED1_A2.2 R126_A2.1 | length 1.8
  Top Layer w0.178: DVDD_LED1_A2.2@187.479,8.113 187.519,8.152 v2(187.519,8.574)
  Bottom Layer w0.178: R126_A2.1@187.468,7.31 187.468,8.524 v2(187.519,8.574)
NetLDOIN_LED1_A1_2: LDOIN_LED1_A1.2 R129_A1.1 | length 1.8
  Top Layer w0.178: LDOIN_LED1_A1.2@80.571,8.062 v2(80.572,8.546)
  Bottom Layer w0.178: R129_A1.1@80.572,7.26 v2(80.572,8.546)
NetLDOIN_LED1_A2_2: LDOIN_LED1_A2.2 R129_A2.1 | length 1.8
  Top Layer w0.178: LDOIN_LED1_A2.2@185.571,8.113 v2(185.572,8.596)
  Bottom Layer w0.178: R129_A2.1@185.572,7.31 v2(185.572,8.596)
NetNFAULT_LED1_A1_2: NFAULT_LED1_A1.2 R130_A1.1 | length 1.3
  Top Layer w0.178: NFAULT_LED1_A1.2@84.517,8.012 84.624,8.119 v2(84.624,8.514)
  Bottom Layer w0.178: R130_A1.1@84.624,7.764 v2(84.624,8.514)
NetNFAULT_LED1_A2_2: NFAULT_LED1_A2.2 R130_A2.1 | length 1.3
  Top Layer w0.178: NFAULT_LED1_A2.2@189.517,8.062 189.624,8.169 v2(189.624,8.564)
  Bottom Layer w0.178: R130_A2.1@189.624,7.814 v2(189.624,8.564)
NetQ1_A1_3: Q1_A1.3 R130_A1.2 | length 10.8
  Top Layer w0.178: Q1_A1.3@75.587,5.965 75.662,5.965 75.723,5.903 75.723,5.854 76.051,5.526 77.253,5.526 77.347,5.62 80.551,5.62 80.995,5.176 84.2,5.176 84.483,4.892 v1(84.491,4.892)
  Bottom Layer w0.254: v1(84.491,4.892) 84.491,6.031 R130_A1.2@84.624,6.164
NetQ1_A2_3: Q1_A2.3 R130_A2.2 | length 10.8
  Top Layer w0.178: Q1_A2.3@180.587,6.015 180.662,6.015 180.723,5.953 180.723,5.904 181.051,5.576 182.253,5.576 182.347,5.67 185.551,5.67 185.995,5.226 189.2,5.226 189.483,4.942 v1(189.491,4.942)
  Bottom Layer w0.254: v1(189.491,4.942) 189.491,6.081 R130_A2.2@189.624,6.214
NetR70_A1_1: R70_A1.1 U4_A1.3 | length 1.6
  Bottom Layer w0.305: R70_A1.1@59.887,24.206 59.952,24.141 59.952,23.215 60.25,22.917 U4_A1.3@60.25,22.717
NetR70_A2_1: R70_A2.1 U4_A2.3 | length 1.6
  Bottom Layer w0.305: R70_A2.1@164.887,24.256 164.952,24.191 164.952,23.265 165.25,22.967 U4_A2.3@165.25,22.767
NetR127_A1_2: R127_A1.2 TSREF_LED1_A1.2 | length 2.3
  Top Layer w0.305: v1(60.292,30.403) TSREF_LED1_A1.2@60.292,31.384
  Bottom Layer w0.178: v1(60.292,30.403) R127_A1.2@60.292,31.671 R127_A1.2@60.292,31.696
NetR127_A2_2: R127_A2.2 TSREF_LED1_A2.2 | length 2.3
  Top Layer w0.305: v1(165.292,30.453) TSREF_LED1_A2.2@165.293,31.434
  Bottom Layer w0.178: v1(165.292,30.453) R127_A2.2@165.292,31.721 R127_A2.2@165.292,31.746
PWR_A1: D1_A1.1 J3_A1.10 J5_A1.17 R1_A1.2 R6_A1.1 | length 94.5
  Top Layer w0.381: R1_A1.2@90.658,22.984 90.677,23.003 R6_A1.1@90.677,25.245 90.704,25.272 90.704,36.441 91.988,37.726 117.856,37.726 118.342,38.212 118.342,66.087 115.785,68.644 115.785,72.105 J3_A1.10@114.595,73.295 112.072,75.818 110.693,75.818 107.892,78.619 107.892,80.299 107.833,80.358 107.833,82.779 v1(107.799,82.813)
  Bottom Layer w0.381: v1(107.799,82.813) 107.799,82.861 108.346,83.408 108.346,83.742 108.431,83.828 109.558,83.828 D1_A1.1@109.917,84.187
PWR_A2: D1_A2.1 J3_A2.10 J5_A2.17 R1_A2.2 R6_A2.1 | length 94.5
  Top Layer w0.381: R1_A2.2@195.658,23.034 195.704,23.08 R6_A2.1@195.704,25.277 195.704,36.491 196.988,37.776 222.856,37.776 223.342,38.262 223.342,66.137 220.785,68.694 220.785,72.155 J3_A2.10@219.595,73.345 217.072,75.868 215.693,75.868 212.892,78.669 212.892,80.349 212.833,80.408 212.833,82.829 v1(212.799,82.863)
  Bottom Layer w0.381: v1(212.799,82.863) 212.799,82.911 213.346,83.458 213.346,83.792 213.431,83.878 214.558,83.878 D1_A2.1@214.917,84.237
REF_A1_P: C30_A1.2 U1_A1.64 | length 2.8
  Top Layer w0.178: C30_A1.2@66.704,25.129 67.284,24.549 67.284,24.437 67.673,24.049 U1_A1.64@68.982,24.049
REF_A2_P: C30_A2.2 U1_A2.64 | length 2.8
  Top Layer w0.178: C30_A2.2@171.704,25.179 172.284,24.599 172.284,24.487 172.673,24.099 U1_A2.64@173.982,24.099
SRN_IN_A1: C39_A1.2 C40_A1.2 J11_A1.1 R57_A1.2 | length 49.7
  Top Layer w0.178: J11_A1.1@30.413,11.955 30.413,9.735 34.949,5.199 69.974,5.199 72.126,7.351 C39_A1.2@72.151,7.351 ; R57_A1.2@72.629,8.608 72.608,8.586 72.608,8.104 72.562,8.059 72.562,7.737 72.176,7.351 C39_A1.2@72.151,7.351 ; C40_A1.2@73.567,7.112 72.39,7.112 C39_A1.2@72.151,7.351
SRN_IN_A2: C39_A2.2 C40_A2.2 J11_A2.1 R57_A2.2 | length 49.7
  Top Layer w0.178: J11_A2.1@135.413,12.005 135.413,9.785 139.949,5.249 174.974,5.249 177.126,7.401 C39_A2.2@177.151,7.401 ; R57_A2.2@177.531,8.625 177.608,8.548 177.608,8.124 177.562,8.078 177.562,7.787 177.176,7.401 C39_A2.2@177.151,7.401 ; C40_A2.2@178.567,7.162 177.39,7.162 C39_A2.2@177.151,7.401
SRP_IN_A1: C33_A1.1 C39_A1.1 J11_A1.2 R55_A1.2 | length 46.6
  Top Layer w0.178: J11_A1.2@32.413,11.955 32.413,9.147 35.983,5.577 69.524,5.577 70.297,6.349 70.401,6.454 70.401,7.201 C39_A1.1@70.551,7.351 ; C33_A1.1@69.228,7.039 69.39,7.2 69.634,7.2 69.784,7.351 C39_A1.1@70.551,7.351 ; R55_A1.2@71.154,8.61 71.062,8.518 71.062,7.837 70.576,7.351 C39_A1.1@70.551,7.351
SRP_IN_A2: C33_A2.1 C39_A2.1 J11_A2.2 R55_A2.2 | length 46.5
  Top Layer w0.178: J11_A2.2@137.413,12.005 137.413,9.197 140.983,5.627 174.524,5.627 175.297,6.399 175.401,6.504 175.401,7.251 C39_A2.1@175.551,7.401 ; C33_A2.1@174.228,7.089 174.39,7.25 174.634,7.25 174.784,7.401 C39_A2.1@175.551,7.401 ; R55_A2.2@176.056,8.628 176.062,8.621 176.062,7.887 175.576,7.401 C39_A2.1@175.551,7.401
SW_A1: D3_A1.1 L2_A1.1 R20_A1.2 R50_A1.1 U1_A1.99 | length 4.5
  Top Layer w0.178: 80.057,16.861 U1_A1.99@80.057,17.774
  Top Layer w0.305: L2_A1.1@79.993,13.29 80.057,13.354 80.057,16.861
SW_A2: D3_A2.1 L2_A2.1 R20_A2.2 R50_A2.1 U1_A2.99 | length 4.5
  Top Layer w0.178: 185.057,16.911 U1_A2.99@185.057,17.824
  Top Layer w0.305: L2_A2.1@184.993,13.34 185.057,13.404 185.057,16.911
TS1_A1: C102_A1.2 J4_A1.1 R173_A1.1 R180_A1.2 R181_A1.1 | length 81.1
  Top Layer w0.178: v1(25.715,82.712) 25.715,82.659 25.942,82.432 J4_A1.1@25.942,80.587 25.942,77.485 23.198,74.741 23.198,38.751 26.028,35.92 46.738,35.92 47.348,35.311 47.348,31.257 47.244,31.153 R173_A1.1@46.759,31.153 R180_A1.2@46.759,29.651
  Bottom Layer w0.178: R181_A1.1@25.217,86.612 25.217,85.297 25.176,85.255 25.176,84.251 C102_A1.2@25.715,83.712 v1(25.715,82.712)
TS1_A2: C102_A2.2 J4_A2.1 R173_A2.1 R180_A2.2 R181_A2.1 | length 81.1
  Top Layer w0.178: v1(130.715,82.762) 130.715,82.709 130.942,82.482 J4_A2.1@130.942,80.637 130.942,77.535 128.198,74.791 128.198,38.801 131.028,35.97 151.738,35.97 152.348,35.361 152.348,31.307 152.244,31.203 R173_A2.1@151.759,31.203 R180_A2.2@151.759,29.701
  Bottom Layer w0.178: R181_A2.1@130.217,86.662 130.217,85.347 130.176,85.305 130.176,84.301 C102_A2.2@130.715,83.762 ; v1(130.715,82.762) C102_A2.2@130.715,83.762
TS1_MUX_A1: C77_A1.1 R180_A1.1 U3_A1.5 | length 10.6
  Top Layer w0.178: R180_A1.1@46.759,28.451 46.759,26.944 C77_A1.1@46.781,26.922 46.242,26.383 46.242,24.57 46.843,23.97 46.843,22.483 46.776,22.416 46.776,20.911 46.968,20.719 49.228,20.719 49.233,20.724 U3_A1.5@49.243,20.724
TS1_MUX_A2: C77_A2.1 R180_A2.1 U3_A2.5 | length 10.6
  Top Layer w0.178: R180_A2.1@151.759,28.501 151.759,26.994 C77_A2.1@151.781,26.972 151.242,26.433 151.242,24.62 151.843,24.02 151.843,22.533 151.776,22.466 151.776,20.961 151.968,20.769 154.228,20.769 154.233,20.774 U3_A2.5@154.243,20.774
TS2_A1: C95_A1.2 J4_A1.22 R175_A1.1 R176_A1.2 R177_A1.1 | length 82.6
  Top Layer w0.178: v1(26.885,82.712) 26.885,80.644 J4_A1.22@26.942,80.587 26.942,77.809 23.576,74.443 23.576,38.907 26.185,36.298 48.291,36.298 48.699,35.889 48.699,31.257 48.595,31.153 R175_A1.1@48.11,31.153 R176_A1.2@48.11,29.651
  Bottom Layer w0.178: R177_A1.1@26.584,86.612 26.373,86.401 26.373,85.332 26.351,85.311 26.351,84.276 26.415,84.212 26.415,84.187 C95_A1.2@26.89,83.712 26.888,83.71 v1@26.888,82.714
TS2_A2: C95_A2.2 J4_A2.22 R175_A2.1 R176_A2.2 R177_A2.1 | length 82.6
  Top Layer w0.178: v1(131.885,82.762) 131.885,80.694 J4_A2.22@131.942,80.637 131.942,77.859 128.576,74.493 128.576,38.957 131.185,36.348 153.291,36.348 153.699,35.939 153.699,31.307 153.595,31.203 R175_A2.1@153.11,31.203 R176_A2.2@153.11,29.701
  Bottom Layer w0.178: R177_A2.1@131.584,86.662 131.373,86.451 131.373,85.382 131.351,85.361 131.351,84.326 131.415,84.262 131.415,84.237 C95_A2.2@131.89,83.762 131.888,83.76 v1@131.888,82.764
TS2_MUX_A1: C81_A1.1 R176_A1.1 U3_A1.4 | length 9.5
  Top Layer w0.178: R176_A1.1@48.11,28.451 48.098,28.451 48.055,28.408 48.055,26.994 C81_A1.1@48.127,26.922 47.716,26.511 47.707,26.511 47.516,26.32 47.516,24.216 47.22,23.921 47.22,22.327 47.153,22.26 47.153,21.634 47.46,21.327 47.894,21.327 47.955,21.388 49.229,21.388 U3_A1.4@49.243,21.374
TS2_MUX_A2: C81_A2.1 R176_A2.1 U3_A2.4 | length 9.5
  Top Layer w0.178: R176_A2.1@153.11,28.501 153.098,28.501 153.055,28.458 153.055,27.044 C81_A2.1@153.127,26.972 152.716,26.561 152.707,26.561 152.516,26.37 152.516,24.266 152.22,23.971 152.22,22.377 152.153,22.31 152.153,21.684 152.46,21.377 152.894,21.377 152.955,21.438 154.229,21.438 U3_A2.4@154.243,21.424
TS3_A1: C98_A1.2 J4_A1.2 R174_A1.1 R178_A1.2 R179_A1.1 | length 84.1
  Top Layer w0.178: v1(28.056,82.712) 28.056,80.7 J4_A1.2@27.942,80.587 27.853,80.498 27.853,78.045 23.954,74.145 23.954,39.064 26.341,36.676 49.54,36.676 50.051,36.165 50.051,31.257 49.946,31.153 R174_A1.1@49.462,31.153 R178_A1.2@49.462,29.651
  Bottom Layer w0.178: R179_A1.1@27.951,86.612 27.74,86.401 27.74,85.662 27.429,85.351 27.429,84.349 C98_A1.2@28.066,83.712 28.061,83.707 v1@28.061,82.717
TS3_A2: C98_A2.2 J4_A2.2 R174_A2.1 R178_A2.2 R179_A2.1 | length 84.1
  Top Layer w0.178: v1(133.056,82.762) 133.056,80.75 J4_A2.2@132.942,80.637 132.853,80.548 132.853,78.095 128.954,74.195 128.954,39.114 131.341,36.726 154.54,36.726 155.051,36.215 155.051,31.307 154.946,31.203 R174_A2.1@154.462,31.203 R178_A2.2@154.462,29.701
  Bottom Layer w0.178: R179_A2.1@132.951,86.662 132.74,86.451 132.74,85.712 132.429,85.401 132.429,84.399 C98_A2.2@133.066,83.762 133.061,83.757 v1@133.061,82.767
TS3_MUX_A1: C80_A1.1 R178_A1.1 U3_A1.2 | length 7.3
  Top Layer w0.178: U3_A1.2@49.243,22.674 48.308,22.674 48.204,22.778 48.204,24.092 48.716,24.604 48.716,26.164 49.063,26.511 49.071,26.511 C80_A1.1@49.483,26.922 49.482,27.022 49.411,27.094 49.411,28.394 49.411,28.4 R178_A1.1@49.462,28.451
TS3_MUX_A2: C80_A2.1 R178_A2.1 U3_A2.2 | length 7.3
  Top Layer w0.178: U3_A2.2@154.243,22.724 153.308,22.724 153.204,22.828 153.204,24.142 153.716,24.654 153.716,26.214 154.063,26.561 154.071,26.561 C80_A2.1@154.483,26.972 154.482,27.072 154.411,27.144 154.411,28.444 154.411,28.45 R178_A2.1@154.462,28.501
TS4_A1: C104_A1.2 J4_A1.23 R172_A1.1 R182_A1.2 R183_A1.1 | length 85.6
  Top Layer w0.178: v1(29.226,82.712) 28.942,82.428 J4_A1.23@28.942,80.587 28.853,80.498 28.853,78.369 24.331,73.847 24.331,39.22 26.498,37.054 50.783,37.054 51.402,36.435 51.402,31.257 51.298,31.153 R172_A1.1@50.813,31.153 50.76,31.1 R182_A1.2@50.76,29.593
  Bottom Layer w0.178: v1@29.234,82.719 29.234,83.705 C104_A1.2@29.241,83.712 28.604,84.349 28.604,85.623 28.917,85.936 28.917,86.112 29.317,86.512 R183_A1.1@29.317,86.612
TS4_A2: C104_A2.2 J4_A2.23 R172_A2.1 R182_A2.2 R183_A2.1 | length 85.6
  Top Layer w0.178: v1(134.226,82.762) 133.942,82.478 J4_A2.23@133.942,80.637 133.853,80.548 133.853,78.419 129.331,73.897 129.331,39.27 131.498,37.104 155.783,37.104 156.402,36.485 156.402,31.307 156.298,31.203 R172_A2.1@155.813,31.203 155.76,31.15 R182_A2.2@155.76,29.643
  Bottom Layer w0.178: v1@134.234,82.769 134.234,83.755 C104_A2.2@134.241,83.762 133.604,84.399 133.604,85.673 133.917,85.986 133.917,86.162 134.317,86.562 R183_A2.1@134.317,86.662
TS4_MUX_A1: C76_A1.1 R182_A1.1 U3_A1.1 | length 6.3
  Top Layer w0.178: U3_A1.1@49.243,23.324 49.379,23.46 50.116,23.46 50.154,23.498 50.154,26.254 50.412,26.511 50.421,26.511 C76_A1.1@50.832,26.922 C76_A1.1@50.832,27.022 ; R182_A1.1@50.813,28.451 50.773,28.411 50.773,28.38 50.773,27.023 C76_A1.1@50.832,26.964
TS4_MUX_A2: C76_A2.1 R182_A2.1 U3_A2.1 | length 6.3
  Top Layer w0.178: U3_A2.1@154.243,23.374 154.379,23.51 155.116,23.51 155.154,23.548 155.154,26.304 155.412,26.561 155.421,26.561 C76_A2.1@155.832,26.972 C76_A2.1@155.832,27.072 ; R182_A2.1@155.813,28.501 155.773,28.461 155.773,28.43 155.773,27.073 C76_A2.1@155.832,27.014
TS5_A1: C108_A1.2 J4_A1.3 R170_A1.1 R186_A1.2 R187_A1.1 | length 87
  Top Layer w0.178: v1(30.388,82.712) 30.388,82.609 30.203,82.424 30.203,80.848 J4_A1.3@29.942,80.587 29.853,80.498 29.853,78.693 24.709,73.549 24.709,39.377 26.654,37.431 52.334,37.431 52.753,37.012 52.753,31.257 52.649,31.153 R170_A1.1@52.164,31.153 R186_A1.2@52.164,29.651
  Bottom Layer w0.178: v1@30.402,82.726 30.402,83.698 C108_A1.2@30.416,83.712 29.877,84.251 29.877,85.082 30.284,85.488 30.284,86.112 30.684,86.512 R187_A1.1@30.684,86.612
TS5_A2: C108_A2.2 J4_A2.3 R170_A2.1 R186_A2.2 R187_A2.1 | length 87
  Top Layer w0.178: v1(135.388,82.762) 135.388,82.659 135.203,82.474 135.203,80.898 J4_A2.3@134.942,80.637 134.853,80.548 134.853,78.743 129.709,73.599 129.709,39.427 131.654,37.481 157.334,37.481 157.753,37.062 157.753,31.307 157.649,31.203 R170_A2.1@157.164,31.203 R186_A2.2@157.164,29.701
  Bottom Layer w0.178: v1@135.402,82.776 135.402,83.748 C108_A2.2@135.416,83.762 134.877,84.301 134.877,85.132 135.284,85.538 135.284,86.162 135.684,86.562 R187_A2.1@135.684,86.662
TS5_MUX_A1: C72_A1.1 R186_A1.1 U3_A1.15 | length 9.5
  Top Layer w0.178: U3_A1.15@55.043,22.674 54.992,22.623 51.94,22.623 51.573,22.99 51.573,26.342 51.742,26.511 51.751,26.511 C72_A1.1@52.162,26.922 52.162,27.022 52.14,27.044 52.14,28.272 52.09,28.322 R186_A1.1@52.09,28.377 ; R186_A1.1@52.09,28.377 R186_A1.1@52.164,28.451 R186_A1.1@52.09,28.377
TS5_MUX_A2: C72_A2.1 R186_A2.1 U3_A2.15 | length 9.5
  Top Layer w0.178: U3_A2.15@160.043,22.724 159.992,22.673 156.94,22.673 156.573,23.04 156.573,26.392 156.742,26.561 156.751,26.561 C72_A2.1@157.162,26.972 157.162,27.072 157.14,27.094 157.14,28.322 157.09,28.372 R186_A2.1@157.09,28.427 ; R186_A2.1@157.09,28.427 R186_A2.1@157.164,28.501 R186_A2.1@157.09,28.427
TS6_A1: C112_A1.2 J4_A1.24 R169_A1.1 R188_A1.2 R189_A1.1 | length 88.3
  Top Layer w0.178: v1(31.577,82.729) 31.577,82.703 31.203,82.33 31.203,80.848 30.853,80.498 30.853,79.018 25.087,73.251 25.087,39.533 26.811,37.809 53.123,37.809 54.13,36.802 54.13,31.283 54,31.153 R169_A1.1@53.515,31.153 R188_A1.2@53.515,29.651
  Bottom Layer w0.178: v1@31.579,82.724 31.579,83.7 C112_A1.2@31.592,83.712 30.99,84.314 30.99,85.126 31.651,85.786 31.651,86.112 32.051,86.512 R189_A1.1@32.051,86.612
TS6_A2: C112_A2.2 J4_A2.24 R169_A2.1 R188_A2.2 R189_A2.1 | length 88.3
  Top Layer w0.178: v1(136.577,82.779) 136.577,82.753 136.203,82.38 136.203,80.898 135.853,80.548 135.853,79.068 130.087,73.301 130.087,39.583 131.811,37.859 158.123,37.859 159.13,36.852 159.13,31.333 159,31.203 R169_A2.1@158.515,31.203 R188_A2.2@158.515,29.701
  Bottom Layer w0.178: v1@136.579,82.774 136.579,83.75 C112_A2.2@136.592,83.762 135.99,84.364 135.99,85.176 136.651,85.836 136.651,86.162 137.051,86.562 R189_A2.1@137.051,86.662
TS6_MUX_A1: C69_A1.1 R188_A1.1 U3_A1.14 | length 9.9
  Top Layer w0.178: C69_A1.1@53.331,27.022 53.331,28.342 53.44,28.451 R188_A1.1@53.515,28.451 ; C69_A1.1@53.403,26.913 53.969,26.913 54.075,26.807 54.075,25.067 54.18,24.962 54.222,24.962 54.391,24.793 54.391,24.636 54.703,24.325 55.748,24.325 56.446,23.627 56.446,22.51 55.898,21.963 55.104,21.963 U3_A1.14@55.043,22.024 ; C69_A1.1@53.403,26.968 C69_A1.1@53.403,27.022
TS6_MUX_A2: C69_A2.1 R188_A2.1 U3_A2.14 | length 9.9
  Top Layer w0.178: C69_A2.1@158.331,27.072 158.331,28.392 158.44,28.501 R188_A2.1@158.515,28.501 ; C69_A2.1@158.403,26.963 158.969,26.963 159.075,26.857 159.075,25.117 159.18,25.012 159.222,25.012 159.391,24.843 159.391,24.686 159.703,24.375 160.748,24.375 161.446,23.677 161.446,22.56 160.898,22.013 160.104,22.013 U3_A2.14@160.043,22.074 ; C69_A2.1@158.403,27.018 C69_A2.1@158.403,27.072
TS7_A1: C114_A1.2 J4_A1.4 R168_A1.1 R190_A1.2 R191_A1.1 | length 90.1
  Top Layer w0.178: v1(32.769,82.723) 32.699,82.723 32.303,82.328 32.303,82.248 31.942,81.887 J4_A1.4@31.942,80.587 31.581,80.226 31.581,78.846 31.383,78.648 31.159,78.648 25.465,72.953 25.465,39.69 26.967,38.187 54.548,38.187 55.456,37.279 55.456,31.257 55.351,31.153 R168_A1.1@54.867,31.153 R190_A1.2@54.867,29.651
  Bottom Layer w0.178: C114_A1.2@32.767,83.712 32.131,84.348 32.131,85.198 32.478,85.545 32.627,85.545 33.017,85.936 33.017,86.112 33.417,86.512 R191_A1.1@33.417,86.612 ; v1@32.768,82.724 C114_A1.2@32.768,83.711
TS7_A2: C114_A2.2 J4_A2.4 R168_A2.1 R190_A2.2 R191_A2.1 | length 90.1
  Top Layer w0.178: v1(137.769,82.773) 137.699,82.773 137.303,82.378 137.303,82.298 136.942,81.937 J4_A2.4@136.942,80.637 136.581,80.276 136.581,78.896 136.383,78.698 136.159,78.698 130.465,73.003 130.465,39.74 131.967,38.237 159.548,38.237 160.456,37.329 160.456,31.307 160.351,31.203 R168_A2.1@159.867,31.203 R190_A2.2@159.867,29.701
  Bottom Layer w0.178: C114_A2.2@137.767,83.762 137.131,84.398 137.131,85.248 137.478,85.595 137.627,85.595 138.017,85.986 138.017,86.162 138.417,86.562 R191_A2.1@138.417,86.662 ; v1@137.768,82.774 C114_A2.2@137.767,83.762
TS7_MUX_A1: C68_A1.1 R190_A1.1 U3_A1.13 | length 9.5
  Top Layer w0.178: R190_A1.1@54.867,28.451 54.664,28.249 54.664,27.022 C68_A1.1@54.664,26.922 55.075,26.511 55.084,26.511 55.471,26.125 55.471,25.367 55.646,25.192 55.646,24.86 55.751,24.756 56.231,24.756 56.824,24.163 56.824,22.354 55.98,21.51 55.179,21.51 U3_A1.13@55.043,21.374
TS7_MUX_A2: C68_A2.1 R190_A2.1 U3_A2.13 | length 9.5
  Top Layer w0.178: R190_A2.1@159.867,28.501 159.664,28.299 159.664,27.072 C68_A2.1@159.664,26.972 160.075,26.561 160.084,26.561 160.471,26.175 160.471,25.417 160.646,25.242 160.646,24.91 160.751,24.806 161.231,24.806 161.824,24.213 161.824,22.404 160.98,21.56 160.179,21.56 U3_A2.13@160.043,21.424
TS8_A1: C82_A1.2 J5_A1.1 R136_A1.1 R146_A1.2 R147_A1.1 | length 127.7
  Top Layer w0.178: v1(74.897,83.204) 74.897,83.197 75.531,82.563 75.531,82.348 75.892,81.987 J5_A1.1@75.892,80.687
  Bottom Layer w0.178: R146_A1.2@44.997,29.901 44.997,31.064 R136_A1.1@45.066,31.133 ; R136_A1.1@44.997,31.133 44.997,31.151 44.855,31.293 44.786,31.293 44.786,31.489 44.682,31.593 44.578,31.593 43.972,32.199 43.972,34.56 43.852,34.68 42.829,34.68 42.74,34.769 26.061,34.769 21.298,39.532 21.298,72.764 30.32,81.787 32.767,81.787 73.48,81.787 v1(74.897,83.204) ; R147_A1.1@74.867,86.137 74.892,86.112 74.892,83.912 ; v1@74.892,83.2 74.892,83.912 ; C82_A1.2@75.592,83.912 74.892,83.912
TS8_A2: C82_A2.2 J5_A2.1 R136_A2.1 R146_A2.2 R147_A2.1 | length 127.7
  Top Layer w0.178: v1(179.897,83.254) 179.897,83.247 180.531,82.613 180.531,82.398 180.892,82.037 J5_A2.1@180.892,80.737
  Bottom Layer w0.178: R146_A2.2@149.997,29.951 149.997,31.114 R136_A2.1@150.066,31.183 ; R136_A2.1@149.997,31.183 149.997,31.201 149.855,31.343 149.786,31.343 149.786,31.539 149.682,31.643 149.578,31.643 148.972,32.249 148.972,34.61 148.852,34.73 147.829,34.73 147.74,34.819 131.061,34.819 126.298,39.582 126.298,72.814 135.32,81.837 137.767,81.837 178.48,81.837 v1(179.897,83.254) ; R147_A2.1@179.867,86.187 179.892,86.162 179.892,83.962 ; v1@179.892,83.25 179.892,83.962 ; C82_A2.2@180.592,83.962 179.892,83.962
TS8_MUX_A1: C64_A1.1 R146_A1.1 U2_A1.5 | length 11.8
  Bottom Layer w0.178: R146_A1.1@44.997,28.701 C64_A1.1@44.997,27.065 45.409,26.654 45.417,26.654 45.952,26.119 45.952,24.971 46.947,23.976 46.947,23.945 47.278,23.613 49.656,23.613 49.76,23.509 49.76,21.522 49.513,21.275 48.809,21.275 U2_A1.5@48.673,21.139
TS8_MUX_A2: C64_A2.1 R146_A2.1 U2_A2.5 | length 11.8
  Bottom Layer w0.178: R146_A2.1@149.997,28.751 C64_A2.1@149.997,27.115 150.409,26.704 150.417,26.704 150.952,26.169 150.952,25.021 151.947,24.026 151.947,23.995 152.278,23.663 154.656,23.663 154.76,23.559 154.76,21.572 154.513,21.325 153.809,21.325 U2_A2.5@153.673,21.189
TS9_A1: C74_A1.2 J5_A1.22 R138_A1.1 R140_A1.2 R141_A1.1 | length 129.5
  Top Layer w0.178: v1(76.274,83.2) 76.892,82.582 J5_A1.22@76.892,80.687
  Bottom Layer w0.178: R140_A1.2@46.491,29.901 46.486,29.906 R138_A1.1@46.486,31.171 46.486,31.271 46.074,31.682 46.066,31.682 45.741,32.006 45.741,34.884 45.567,35.058 42.986,35.058 42.57,35.474 25.891,35.474 21.676,39.689 21.676,72.608 30.477,81.409 32.767,81.409 74.482,81.409 v1(76.274,83.2) 76.274,83.937 ; R141_A1.1@76.298,86.137 76.274,86.113 76.274,83.937 ; C74_A1.2@76.842,83.937 76.274,83.937
TS9_A2: C74_A2.2 J5_A2.22 R138_A2.1 R140_A2.2 R141_A2.1 | length 129.5
  Top Layer w0.178: v1(181.274,83.25) 181.892,82.632 J5_A2.22@181.892,80.737
  Bottom Layer w0.178: R140_A2.2@151.491,29.951 151.486,29.956 R138_A2.1@151.486,31.221 151.486,31.321 151.074,31.732 151.066,31.732 150.741,32.056 150.741,34.934 150.567,35.108 147.986,35.108 147.57,35.524 130.891,35.524 126.676,39.739 126.676,72.658 135.477,81.459 137.767,81.459 179.482,81.459 v1(181.274,83.25) 181.274,83.987 ; R141_A2.1@181.298,86.187 181.274,86.163 181.274,83.987 ; C74_A2.2@181.842,83.987 181.274,83.987
TS9_MUX_A1: C66_A1.1 R140_A1.1 U2_A1.4 | length 12.4
  Bottom Layer w0.178: R140_A1.1@46.491,28.701 46.491,27.165 C66_A1.1@46.491,27.065 46.902,26.654 46.91,26.654 47.331,26.234 47.331,24.095 47.435,23.991 49.97,23.991 50.389,23.572 50.389,21.501 49.513,20.625 48.809,20.625 U2_A1.4@48.673,20.489
TS9_MUX_A2: C66_A2.1 R140_A2.1 U2_A2.4 | length 12.4
  Bottom Layer w0.178: R140_A2.1@151.491,28.751 151.491,27.215 C66_A2.1@151.491,27.115 151.902,26.704 151.91,26.704 152.331,26.284 152.331,24.145 152.435,24.041 154.97,24.041 155.389,23.622 155.389,21.551 154.513,20.675 153.809,20.675 U2_A2.4@153.673,20.539
TS10_A1: C78_A1.2 J5_A1.2 R137_A1.1 R143_A1.2 R144_A1.1 | length 131.7
  Top Layer w0.178: v1(77.649,83.2) 77.649,83.097 77.892,82.854 J5_A1.2@77.892,80.687
  Bottom Layer w0.178: R143_A1.2@47.984,29.901 47.974,29.912 R137_A1.1@47.974,31.171 47.974,31.271 47.562,31.682 47.554,31.682 47.348,31.888 47.348,35.311 47.223,35.436 43.142,35.436 42.727,35.851 26.047,35.851 22.053,39.845 22.053,72.451 30.633,81.031 32.767,81.031 75.48,81.031 v1(77.649,83.2) 77.649,83.962 ; R144_A1.1@77.624,86.137 77.649,86.112 77.649,83.962 ; C78_A1.2@78.317,83.962 77.649,83.962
